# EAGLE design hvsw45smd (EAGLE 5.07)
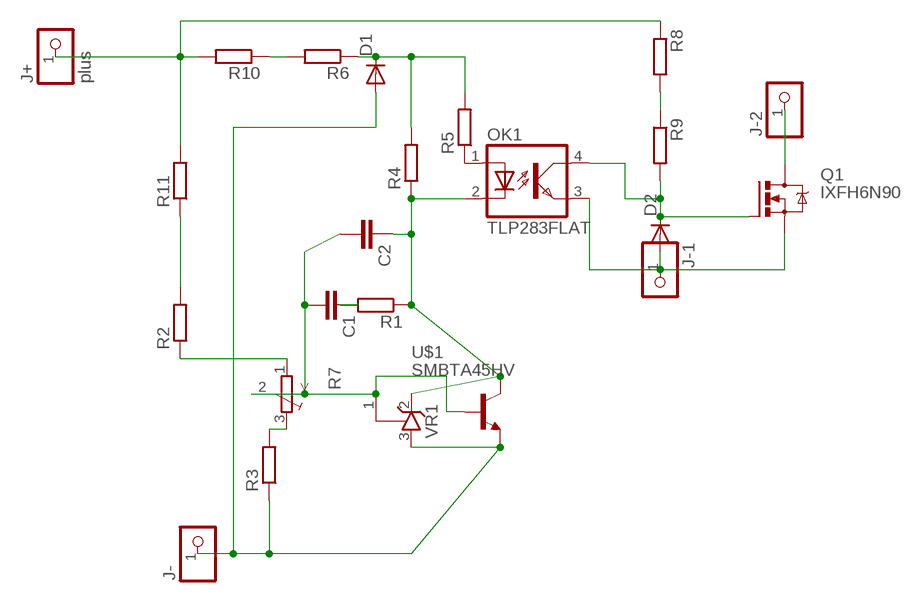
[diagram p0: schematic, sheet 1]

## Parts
C1  C-EUC0805  [C0805]
C2  C-EUC0805  [C0805]
D1  DIODE-MINIMELF  [MINIMELF]
D2  DIODE-MINIMELF  [MINIMELF]
J+  plus  PINHD-1X11X0.4  [1X01]
J-  PINHD-1X11X0.4  [1X01]
J-1  PINHD-1X11X0.4  [1X01]
J-2  PINHD-1X11X0.4  [1X01]
OK1  TLP283FLAT  [FLAT-4]
Q1  IXFH6N90  [TO-247AD-V]
R1  R-EU_R0805  [R0805]
R2  R-EU_R1206  [R1206]
R3  R-EU_R0805  [R0805]
R4  R-EU_R0805  [R0805]
R5  R-EU_R0805  [R0805]
R6  R-EU_R1206  [R1206]
R7  TRIM_EU-3223G  [3223G]
R8  R-EU_R1206  [R1206]
R9  R-EU_R1206  [R1206]
R10  R-EU_R1206  [R1206]
R11  R-EU_R1206  [R1206]
U$1  SMBTA45HV  [SOT23HV]
VR1  TL431CLPSOT23  [SOT23]

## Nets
N$1: D1.A J-.1 R3.1 U$1.2(E) VR1.3(A)
N$2: C1.2 C2.2 R7.2(S) U$1.1(B) VR1.1(R)
N$3: C1.1 R1.2
N$4: R2.1 R7.1(A)
N$5: J+.1 R8.1 R10.2 R11.2
N$6: C2.1 OK1.2(C) R1.1 R4.1 U$1.3(C) VR1.2(C)
N$7: OK1.1(A) R5.1
N$9: R3.2 R7.3(E)
N$10: D2.A J-1.1 OK1.3(EMIT) Q1.S
N$11: D2.C OK1.4(COL) Q1.G R9.2
N$12: R8.2 R9.1
N$13: J-2.1 Q1.D
N$14: D1.C R4.2 R5.2 R6.1
N$15: R2.2 R11.1
N$16: R6.2 R10.1

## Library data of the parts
C1 C2 = rcl:C-EU: CAPACITOR, European symbol
D1 D2 = diode:DIODE-: DIODE
J+ J- J-1 J-2 = pinhead:PINHD-1X1: PIN HEADER
OK1 = optocoupler:TLP283: TOSHIBA PHOTOCOUPLER GaAs IRED & PHOTO-TRANSISTOR Source: http://www.semicon.toshiba.co.jp/td/en/Opto/Photocoupler/en_20050928_TLP283_datasheet.pdf
Q1 = transistor-power:IXF?6N*: HiPerFET (TM) Power MOSFET N-Channel Enhancement Mode HDMOS Family Source: http://www.ixys.com/91529.pdf
R1-R6 R8-R11 = rcl:R-EU_: RESISTOR, European symbol
R7 = pot:TRIM_EU-: POTENTIOMETER
U$1 = transistor-npn:SMBTA45
VR1 = v-reg:TL431CLP: VOLTAGE REGULATOR

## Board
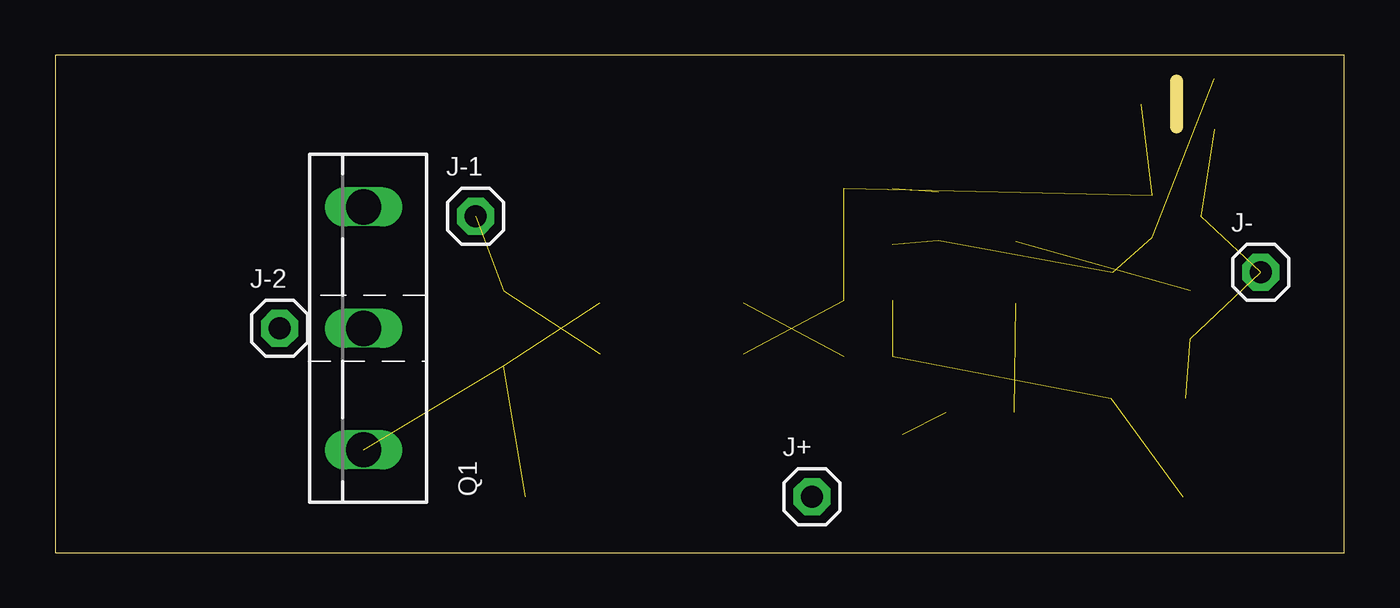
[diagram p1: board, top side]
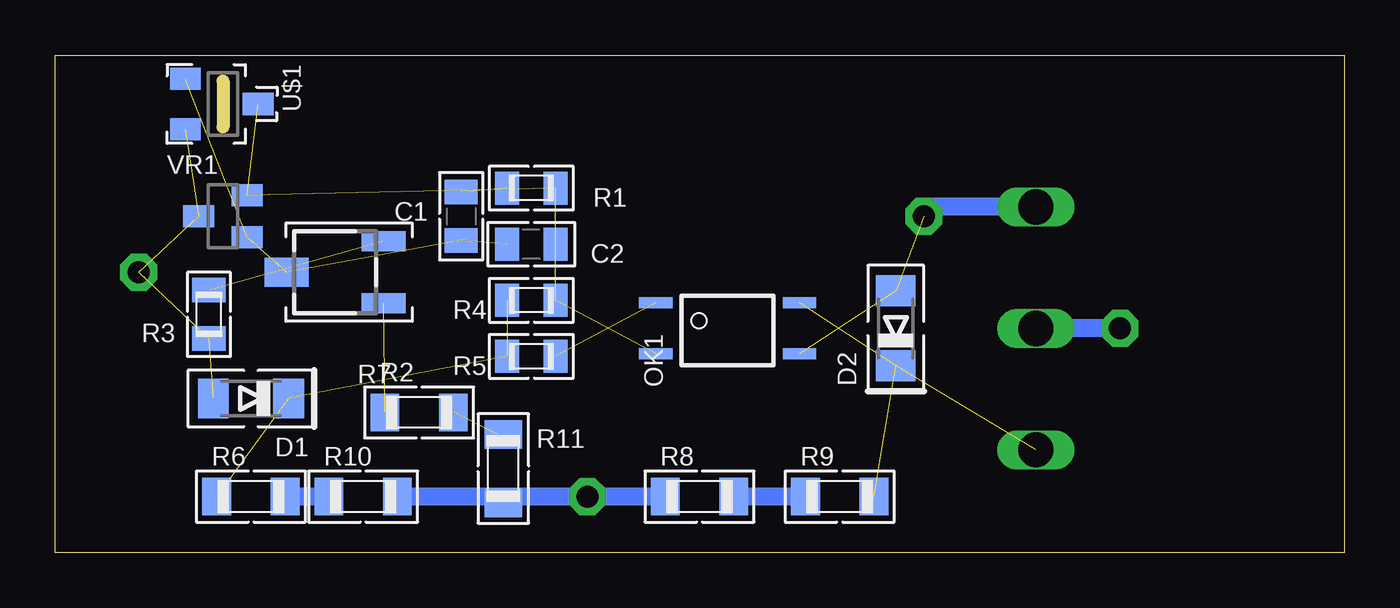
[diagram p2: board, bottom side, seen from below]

Size 58.4 x 22.53 mm. Coordinates in mm from the lower left corner, seen from the top.
Outline: 0,0 58.4,0 58.4,22.53 0,22.53 0,0
Copper layers (1*16): Top 0.035mm / dielectric 1.5mm / Bottom 0.035mm
Design rules "default": minimum track width 10mil, minimum drill 20mil, track to track 8mil, track to pad 8mil, pad to pad 8mil, via to via 8mil, smd to smd 8mil, copper to edge 40mil, drill to drill 8mil, minimum pad ring 1mil, minimum via ring 8mil, stop-mask expansion 4mil, vias tented up to drill 0mil, thermal gap 10mil

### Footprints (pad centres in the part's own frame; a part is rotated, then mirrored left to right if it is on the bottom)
C0805 = smd 1.1 x 1.5: 1 -1.1,0; 2 1.1,0
MINIMELF = smd 1.4 x 1.8: A 1.7,0; C -1.7,0
1X01 = drill 1 pad 1.676 octagon: 1 0,0
FLAT-4 = smd 1.5 x 0.5: 1 -3.25,1.15; 2 -3.25,-1.15; 3 3.25,-1.15; 4 3.25,1.15
TO-247AD-V = drill 1.6 long: D 0,-2.54; G -5.5,-2.54; S 5.5,-2.54
R0805 = smd 1.1 x 1.5: 1 -1.1,0; 2 1.1,0
R1206 = smd 1.3 x 1.7: 1 -1.55,0; 2 1.55,0
3223G = smd 2 x 0.9: 1 -2.2,1.4; 3 -2.2,-1.4 | smd 2 x 1.3: 2 2.2,0
SOT23HV = smd 1 x 1.4: 1 -1.15,-1.7; 2 1.15,-1.7; 3 0,1.6
SOT23 = smd 1 x 1.4: 1 -0.95,-1.1; 2 0.95,-1.1; 3 0,1.1

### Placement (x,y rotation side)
C1  40.01,15.24 270 bottom
C2  36.83,13.97 180 bottom
D1  49.53,6.99 180 bottom
D2  20.32,10.16 90 bottom
J+  34.29,2.54 0 top
J-  54.61,12.7 0 top
J-1  19.05,15.24 0 top
J-2  10.16,10.16 0 top
OK1  27.94,10.16 0 bottom
Q1  11.43,10.16 90 top
R1  36.83,16.51 180 bottom
R2  41.91,6.35 0 bottom
R3  51.44,10.79 90 bottom
R4  36.83,11.43 180 bottom
R5  36.83,8.89 180 bottom
R6  49.53,2.54 0 bottom
R7  45.72,12.7 180 bottom
R8  29.21,2.54 0 bottom
R9  22.86,2.54 0 bottom
R10  44.45,2.54 0 bottom
R11  38.1,3.81 270 bottom
U$1  50.8,20.32 270 bottom
VR1  50.8,15.24 90 bottom

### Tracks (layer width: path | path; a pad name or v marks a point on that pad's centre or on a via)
N$1  (4 unrouted)
N$2  (4 unrouted)
N$3  (1 unrouted)
N$4  (1 unrouted)
N$5
  Bottom 0.813: R8.1 J+.1 38.1,2.54 | 38.1,2.54 R10.2 | 38.1,2.54 R11.2
N$6  (5 unrouted)
N$7  (1 unrouted)
N$9  (1 unrouted)
N$10  (2 unrouted)
  Bottom 0.813: Q1.S 18.63,15.66 J-1.1
N$11  (3 unrouted)
N$12
  Bottom 0.813: R9.1 R8.2
N$13
  Bottom 0.813: J-2.1 Q1.D
N$14  (3 unrouted)
N$15  (1 unrouted)
  Bottom 0.813: R11.1 38.38,5.36
N$16
  Bottom 0.813: R10.1 R6.2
